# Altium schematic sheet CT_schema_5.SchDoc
size 151 x 142 mm
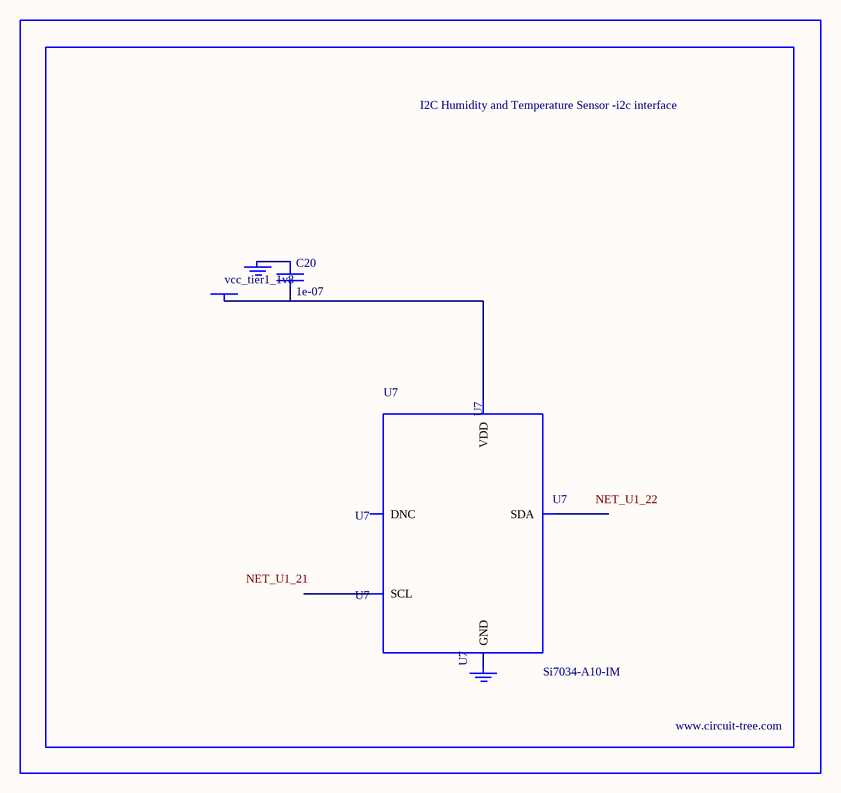
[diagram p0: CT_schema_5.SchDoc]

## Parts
BORDER4  (no value)
C20  1e-07  [C0402]
GND_INSTANCE_4_0  (no value)
GND_INSTANCE_4_1  (no value)
POWER_INSTANCE_4_0  vcc_tier1_1v8
U7  Si7034-A10-IM  [SI7034-A10-IM]

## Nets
NetC20_1: C20.1 GND_INSTANCE_4_0.0(GND)
NetC20_2: C20.2 POWER_INSTANCE_4_0.0(PWR) U7.1(VDD)
NetGND_INSTANCE_4_1_0: GND_INSTANCE_4_1.0(GND) U7.5(GND)

Not connected (* = marked no-connect by the designer): U7 2(SCL) 3(DNC) 4(SDA)

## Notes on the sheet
- Labels drawn without touching a wire or pin: NET_U1_21, NET_U1_22

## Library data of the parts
BORDER4 = BORDER_PAGE4
C20 = C0402C104K3RACTU
GND_INSTANCE_4_0 GND_INSTANCE_4_1 = GND
POWER_INSTANCE_4_0 = PWR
